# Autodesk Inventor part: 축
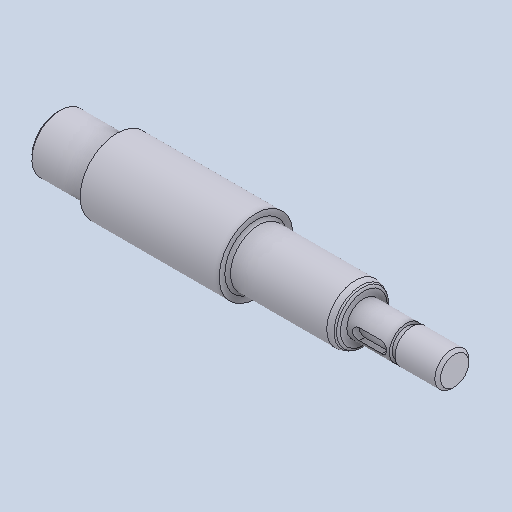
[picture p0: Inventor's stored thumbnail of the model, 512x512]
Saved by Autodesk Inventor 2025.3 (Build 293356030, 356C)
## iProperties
Created: 2025-08
Part Number: 축
Material: 강철, 연강
Document SubType Name: Modeling
Designer: infra011
Density: 7.86 g/cm^3
Appearance: 기본값
Author: jhkim
Sending System: Autodesk Inventor 2026
Preprocessor: ST-DEVELOPER v20.1
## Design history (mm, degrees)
feature "솔리드2"
node "솔리드1"
